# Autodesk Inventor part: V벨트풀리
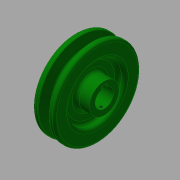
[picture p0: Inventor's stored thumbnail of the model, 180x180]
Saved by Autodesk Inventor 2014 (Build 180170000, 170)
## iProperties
Created: 2015-11
Part Number: V벨트풀리
Material: 강철, 탄소
Document SubType Name: Modeling
Designer: mduedu
Density: 1 g/cm^3
Appearance: 진녹색
Author: mduedu
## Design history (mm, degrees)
sketch "스케치1"
  geometry: L1 (-9.5, 0)-(9.5, 0); L2 (0, 0)-(0, 37.7); L3 (-4.825, 37.7)-(-9.5, 37.7); L4 (-9.5, 37.7)-(-9.5, 0); L5 (0, 28.7)-(-2.074, 28.7); L6 (-2.074, 28.7)-(-4.825, 37.7); L7 (4.825, 37.7)-(9.5, 37.7); L8 (9.5, 37.7)-(9.5, 0); L9 (0, 28.7)-(2.074, 28.7); L10 (2.074, 28.7)-(4.825, 37.7); L11 (-9.5, 35)-(9.5, 35); 3 further points
  constraints: 22 end point, 7 point on line, 4 perpendicular, 3 symmetric about line, 1 coincident, 1 horizontal, 1 horizontal alignment, 1 midpoint, 1 vertical
  dimensions: "d0" = 19 distance of L1.start L1.end; "d2" = 75.4 diameter of L2.end L1 (derived); "d3" = 34 deg angle of L10 L6; "d4" = 6.3 distance between parallel lines of L11 L9; "d5" = 2.7 distance between parallel lines of L7 L11; "d6" = 8 distance of point (4, 35) point (-4, 35); "d7" = 70 diameter of L11 L1
revolve "회전1" sketch "스케치1" stored, may be unused: angle "d8" = 90 deg
sketch "스케치2"
  geometry: C1 r 24 at (0, 0); C2 r 13 at (0, 0); 1 further point
  constraints: 2 centre point, 2 coincident
  dimensions: "d9" = 48 diameter of C1; "d10" = 26 diameter of C2
extrude "돌출1" cut sketch "스케치2" distance "d11" = 6; taper "d12" = 0 deg
extrude "돌출3" join sketch "스케치2" distance "d37" = 6; taper "d38" = 0 deg
fillet "모깎기1" dims "d13" = 3
fillet "모깎기2" dims "d14" = 3
fillet "모깎기3" dims "d15" = 1, "d16" = 0.5, "d17" = 2
hole "구멍1" diameter "d20" = 16; stored, may be unused: countersink angle "d24" = 90 deg, drill point angle "d26" = 118 deg; dims "d21" = 6, "d22" = 4, "d23" = 2, "d25" = 8, "d53" = 10, "d54" = 10
sketch "스케치3"
  geometry: L1 (-2.5, 0)-(2.5, 0); L2 (2.5, 0)-(2.5, 10.3); L3 (2.5, 10.3)-(-2.5, 10.3); L4 (-2.5, 10.3)-(-2.5, 0); 2 further points
  constraints: 8 end point, 2 parallel, 1 coincident, 1 horizontal, 1 midpoint, 1 perpendicular
  dimensions: "d27" = 5 distance of L2.end L3.end; "d29" = 10.3 distance of L3.end L1.start
extrude "돌출2" cut sketch "스케치3" stored distance "d30" = 6; taper "d31" = 0 deg
node "작업 평면1"
sketch "스케치4"
  geometry: L1 (19, -27)-(19, 27) reference; 2 further points
  constraints: 1 horizontal alignment
  dimensions: "d52" = 22 distance from line of L1 point (-3, 0)
hole "구멍2" sketch "스케치4" at (-3, 0) diameter "d42" = 2.459; stored, may be unused: countersink angle "d46" = 90 deg, drill point angle "d48" = 118 deg; dims "d43" = 6, "d44" = 4, "d45" = 2, "d47" = 8
node "솔리드1"
mirror "대칭1"
